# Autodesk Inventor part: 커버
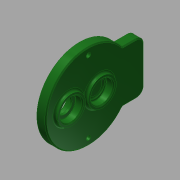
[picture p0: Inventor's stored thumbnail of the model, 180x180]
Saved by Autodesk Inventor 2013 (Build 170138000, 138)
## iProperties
Created: 2016-02
Part Number: 커버
Material: 알루미늄 6061
Document SubType Name: Modeling
Designer: mduedu
Density: 2.71 g/cm^3
Author: mduedu
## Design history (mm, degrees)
sketch "스케치1"
  geometry: C1 r 43 at (0, 0); 1 further point
  constraints: 1 centre point, 1 coincident
  dimensions: "d0" = 86 diameter of C1
extrude "돌출1" new body sketch "스케치1" distance "d1" = 9; taper "d2" = 0 deg
sketch "스케치2"
  geometry: C1 r 14 at (0, 11); 1 further point
  constraints: 1 centre point, 1 vertical alignment
  dimensions: "d3" = 28 diameter of C1; "d6" = 11 distance of C1.centre point (0, 0)
extrude "돌출2" join sketch "스케치2" distance "d7" = 3; taper "d8" = 0 deg
sketch "스케치3"
  geometry: C1 r 14 at (0, -20); 1 further point
  constraints: 1 centre point, 1 vertical alignment
  dimensions: "d9" = 28 diameter of C1; "d10" = 20 distance of C1.centre point (0, 0)
extrude "돌출3" join sketch "스케치3" distance "d11" = 3; taper "d12" = 0 deg
hole "구멍1" diameter "d15" = 22; stored, may be unused: countersink angle "d19" = 90 deg, drill point angle "d21" = 0 deg; dims "d13" = 10, "d14" = 10, "d16" = 6, "d17" = 4, "d18" = 2, "d20" = 7
hole "구멍2" diameter "d24" = 18; stored, may be unused: countersink angle "d28" = 90 deg, drill point angle "d30" = 0 deg; dims "d22" = 10, "d23" = 10, "d25" = 6, "d26" = 4, "d27" = 2, "d29" = 1
hole "구멍3" diameter "d33" = 22; stored, may be unused: countersink angle "d37" = 90 deg, drill point angle "d39" = 0 deg; dims "d34" = 6, "d35" = 4, "d36" = 2, "d38" = 7, "d73" = 10, "d74" = 10
sketch "스케치7"
  geometry: L1 (-26, 34.249)-(26, 34.249); L2 (26, 34.249)-(26, 56); L3 (26, 56)-(-26, 56); L4 (-26, 56)-(-26, 34.249); A1 r 43 centre (0, 0) between (-26, 34.249) and (26, 34.249) reference; 1 further point
  constraints: 8 end point, 2 parallel, 2 point on circle, 1 horizontal, 1 perpendicular
  dimensions: "d95" = 52 distance of L2.end L3.end; "d97" = 56 distance from line of L3 point (0, 0)
extrude "돌출5" join sketch "스케치7" stored distance "d98" = 10; taper "d99" = 0 deg
sketch "스케치4"
  geometry: C1 r 14 at (0, -20) reference; C2 r 18 at (0, -20); 1 further point
  constraints: 1 centre point, 1 coincident
  dimensions: "d40" = 36 diameter of C2
extrude "돌출4" join sketch "스케치4" distance "d41" = 4; taper "d42" = 0 deg
hole "구멍4" diameter "d45" = 22; stored, may be unused: countersink angle "d49" = 90 deg, drill point angle "d51" = 0 deg; dims "d43" = 10, "d44" = 10, "d46" = 6, "d47" = 4, "d48" = 2, "d50" = 7
hole "구멍5" diameter "d54" = 15; stored, may be unused: countersink angle "d58" = 90 deg, drill point angle "d60" = 0 deg; dims "d52" = 10, "d53" = 10, "d55" = 6, "d56" = 4, "d57" = 2, "d59" = 7
fillet "모깎기1" dims "d61" = 0.3
fillet "모깎기2" dims "d62" = 2
chamfer "모따기1" distance "d63" = 1; stored, may be unused: second distance "d64" = 2, angle "d65" = 45 deg
fillet "모깎기6" dims "d88" = 2
sketch "스케치5" dims "d67" = 72
  geometry: 4 further points
  constraints: 2 horizontal alignment, 1 coincident, 5 other
  dimensions: "d71" = 360 deg dimension on point (0, 0) point (-36, 0) (derived)
fillet "모깎기4" dims "d75" = 2
sketch "스케치6"
  geometry: 2 further points
hole "구멍6" sketch "스케치6" at (36, 0), (-36, 0) diameter "d76" = 4.5; stored, may be unused: countersink angle "d80" = 90 deg, drill point angle "d82" = 0 deg; dims "d77" = 6, "d78" = 8, "d79" = 4.6, "d81" = 8
fillet "모깎기7" dims "d100" = 8, "d101" = 2
chamfer "모따기2" distance "d90" = 1; stored, may be unused: second distance "d91" = 2, angle "d92" = 45 deg
node "솔리드1"
node "절단 모서리 투영1"
